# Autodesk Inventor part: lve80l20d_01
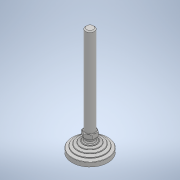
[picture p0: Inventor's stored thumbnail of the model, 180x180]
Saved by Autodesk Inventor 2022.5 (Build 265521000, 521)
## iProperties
Part Number: lve80l20d_01
Material: 一般
Document SubType Name: Modeling
Designer: ImaoCorp
Density: 1 g/cm^3
Appearance: 既定
Author: ImaoCorp
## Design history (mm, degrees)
feature "lve80l20d_01"
node "ソリッド1"
